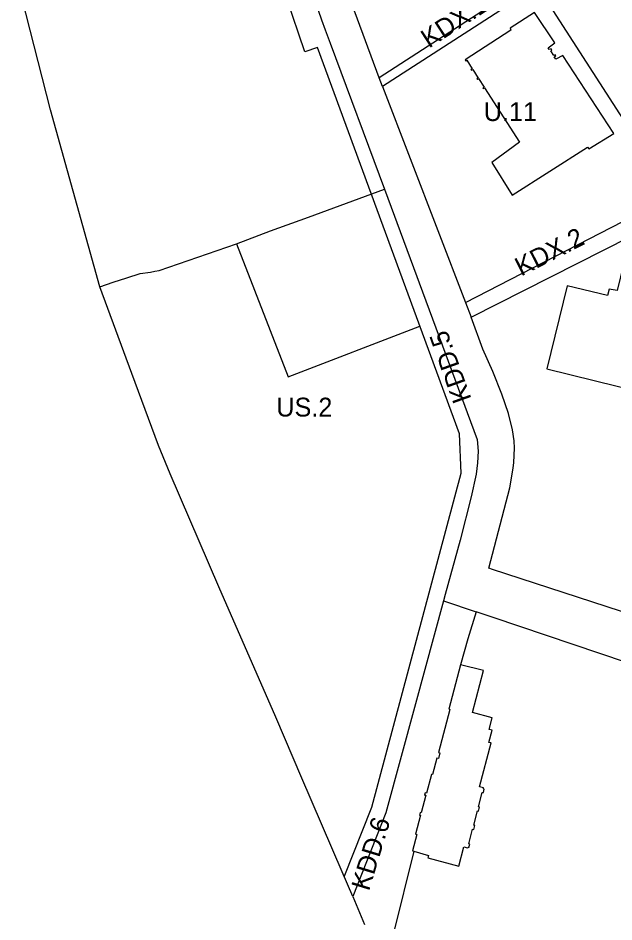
# Model space of a CAD drawing. Extents: x 7424052 to 7425705, y 5546602 to 5547569.
# Drawn here: x 7424707.9 to 7424865.9, y 5546961.1 to 5547200.9 of the extents above; entities that cross this region are included whole.
import ezdxf

# ---------------------------------------------------------------- set-up
doc = ezdxf.new("R2010")
doc.units = 0
for name, color, linetype in [('linia regulacyjna wysokości zabudowy', 7, 'Continuous'), ('linie rozgraniczające', 7, 'Continuous'), ('nieprzekraczalne linie zabudowy', 7, 'Continuous'), ('obowiazujace linie zabudowy', 7, 'Continuous'), ('przeznaczenia terenów', 7, 'Continuous')]:
    doc.layers.add(name, color=color, linetype=linetype)

msp = doc.modelspace()

# ---------------------------------------------------------------- linework, layer by layer
at = {"layer": 'linia regulacyjna wysokości zabudowy'}
msp.add_lwpolyline([(7424765.86, 5547141.04), (7424779.53, 5547105.72), (7424814.48, 5547119.2)], dxfattribs=at)
at = {"layer": 'linie rozgraniczające'}
for p, q in [((7424716.56, 5547176.59), (7424707.94, 5547210.43)), ((7424844.22, 5547211.34), (7424803.72, 5547185.05)), ((7424869.3, 5547172.76), (7424848.08, 5547205.67)), ((7424803.72, 5547185.05), (7424796.45, 5547204.69)), ((7424787.48, 5547203.06), (7424788.42, 5547200.44)), ((7424835.69, 5547202.88), (7424804.56, 5547182.77)), ((7424788.42, 5547200.44), (7424789.37, 5547197.83)), ((7424789.37, 5547197.83), (7424790.69, 5547194.3)), ((7424790.69, 5547194.3), (7424805.06, 5547155.51)), ((7424804.56, 5547182.77), (7424803.72, 5547185.05)), ((7424804.56, 5547182.77), (7424826.56, 5547125.51)), ((7424729.61, 5547129.62), (7424716.56, 5547176.59)), ((7424784.9, 5547148.15), (7424805.06, 5547155.51)), ((7424805.06, 5547155.51), (7424829.65, 5547089.09)), ((7424774.88, 5547144.49), (7424784.9, 5547148.15)), ((7424826.56, 5547125.51), (7424868.31, 5547146.93)), ((7424765.86, 5547141.04), (7424774.88, 5547144.49)), ((7424755.58, 5547137.48), (7424765.86, 5547141.04)), ((7424828.05, 5547121.6), (7424870.34, 5547142.98)), ((7424745.31, 5547133.93), (7424755.58, 5547137.48)), ((7424740.29, 5547133.16), (7424743.02, 5547133.57)), ((7424743.02, 5547133.57), (7424744.16, 5547133.75)), ((7424744.16, 5547133.75), (7424745.31, 5547133.93)), ((7424733.18, 5547130.88), (7424736.73, 5547132.02)), ((7424736.73, 5547132.02), (7424740.29, 5547133.16)), ((7424729.61, 5547129.62), (7424733.18, 5547130.88)), ((7424738.08, 5547106.67), (7424729.61, 5547129.62)), ((7424826.56, 5547125.51), (7424828.05, 5547121.6)), ((7424831.19, 5547113.14), (7424828.05, 5547121.6)), ((7424833.8, 5547107.14), (7424831.19, 5547113.14)), ((7424745.14, 5547087.58), (7424738.08, 5547106.67)), ((7424836.19, 5547101.2), (7424833.8, 5547107.14)), ((7424837.96, 5547096.03), (7424836.19, 5547101.2)), ((7424839.02, 5547091.68), (7424837.96, 5547096.03)), ((7424839.44, 5547088.76), (7424839.02, 5547091.68)), ((7424829.65, 5547089.09), (7424829.94, 5547086.06)), ((7424839.52, 5547086.84), (7424839.44, 5547088.76)), ((7424748.22, 5547080), (7424745.14, 5547087.58)), ((7424829.94, 5547086.06), (7424829.74, 5547082.92)), ((7424839.38, 5547083), (7424839.52, 5547086.84)), ((7424829.74, 5547082.92), (7424829.42, 5547079.97)), ((7424838.36, 5547076.31), (7424839.22, 5547081.54)), ((7424839.22, 5547081.54), (7424839.38, 5547083)), ((7424761.2, 5547050.01), (7424748.22, 5547080)), ((7424829.42, 5547079.97), (7424828.11, 5547073.91)), ((7424832.76, 5547054.97), (7424838.36, 5547076.31)), ((7424828.11, 5547073.91), (7424825.16, 5547062.46)), ((7424825.16, 5547062.46), (7424821.22, 5547047.97)), ((7424833.77, 5547054.64), (7424832.76, 5547054.97)), ((7424878.62, 5547040.03), (7424833.77, 5547054.64)), ((7424776.25, 5547015.45), (7424761.2, 5547050.01)), ((7424821.22, 5547047.97), (7424820.77, 5547046.36)), ((7424820.77, 5547046.36), (7424813.3, 5547018.98)), ((7424820.77, 5547046.36), (7424829.38, 5547043.45)), ((7424813.3, 5547018.98), (7424805.43, 5546990.04)), ((7424805.43, 5546990.04), (7424800.33, 5546977.11)), ((7424800.33, 5546977.11), (7424796.68, 5546967.84)), ((7424796.68, 5546967.84), (7424799.75, 5546960.49))]:
    msp.add_line(p, q, dxfattribs=at)
for points in [[(7424869.23, 5547029.94), (7424833.88, 5547041.92), (7424829.38, 5547043.45), (7424827.17, 5547036.2), (7424825.27, 5547029.34), (7424822.13, 5547017.6), (7424822.38, 5547017.53), (7424819.4, 5547006.12), (7424819.76, 5547005.98), (7424819.38, 5547004.52), (7424818.99, 5547004.59), (7424817.83, 5547000.21), (7424817.53, 5547000.29), (7424816.19, 5546995.34), (7424815.91, 5546995.41), (7424815.74, 5546994.8), (7424816.03, 5546994.73), (7424814.79, 5546990.06), (7424814.51, 5546990.13), (7424814.35, 5546989.5), (7424814.63, 5546989.43), (7424813.32, 5546984.42), (7424813.67, 5546984.35), (7424812.49, 5546980.02), (7424812.89, 5546979.91), (7424807.51, 5546958.13)], [(7424783.14, 5546999.26), (7424776.25, 5547015.45)], [(7424796.68, 5546967.84), (7424793.85, 5546974.41), (7424783.14, 5546999.26)]]:
    msp.add_lwpolyline(points, dxfattribs=at)
at = {"layer": 'nieprzekraczalne linie zabudowy'}
for p, q in [((7424783.94, 5547191.96), (7424774.34, 5547220.72)), ((7424787.32, 5547193.13), (7424783.94, 5547191.96)), ((7424824.94, 5547090.66), (7424787.32, 5547193.13)), ((7424831.6, 5547182.45), (7424840.87, 5547168)), ((7424825.38, 5547080.23), (7424824.94, 5547090.66)), ((7424801.73, 5546991.55), (7424825.38, 5547080.23)), ((7424794.43, 5546973.06), (7424801.73, 5546991.55))]:
    msp.add_line(p, q, dxfattribs=at)
at = {"layer": 'obowiazujace linie zabudowy'}
for points in [[(7424840.87, 5547168), (7424833.52, 5547162.6), (7424838.95, 5547153.99), (7424858.93, 5547166.73), (7424859.28, 5547166.22), (7424865.92, 5547170.35), (7424852.38, 5547191.04), (7424850.51, 5547190.02), (7424850.11, 5547190.64), (7424850.48, 5547190.91), (7424850.31, 5547191.19), (7424850.03, 5547191.04), (7424849.21, 5547192.28), (7424849.44, 5547192.47), (7424849.26, 5547192.74), (7424848.79, 5547192.63), (7424848.5, 5547193.08), (7424850.22, 5547194.37), (7424844.87, 5547202.45), (7424838.45, 5547198.28), (7424838.61, 5547197.75), (7424826.47, 5547189.84), (7424826.62, 5547189.47), (7424826.92, 5547189.75), (7424828.38, 5547187.47), (7424828.02, 5547187.31), (7424828.16, 5547187.1), (7424828.5, 5547187.32), (7424829.94, 5547185.04), (7424829.58, 5547184.89), (7424829.72, 5547184.68), (7424830.06, 5547184.88), (7424831.5, 5547182.61), (7424831.15, 5547182.46), (7424831.29, 5547182.25), (7424831.6, 5547182.45)], [(7424887.39, 5547134.46), (7424869.33, 5547139.19), (7424866.8, 5547128.69), (7424864.65, 5547129.03), (7424864.24, 5547127.34), (7424853.51, 5547129.93), (7424848.1, 5547107.91), (7424891.9, 5547097.08), (7424892.02, 5547097.52), (7424892.6, 5547100.01), (7424895.88, 5547099.43), (7424895.17, 5547096.76), (7424898.36, 5547095.95), (7424897.45, 5547092.28), (7424893.47, 5547076.73), (7424897.15, 5547075.81), (7424903.99, 5547074.05), (7424907.97, 5547089.61), (7424911.02, 5547088.78), (7424910.64, 5547087.2), (7424933.17, 5547081.48), (7424937.27, 5547097.62)], [(7424822.38, 5547017.53), (7424819.4, 5547006.12), (7424819.76, 5547005.98), (7424819.38, 5547004.52), (7424818.99, 5547004.59), (7424817.83, 5547000.21), (7424817.53, 5547000.29), (7424816.19, 5546995.34), (7424815.91, 5546995.41), (7424815.74, 5546994.8), (7424816.03, 5546994.73), (7424814.79, 5546990.06), (7424814.51, 5546990.13), (7424814.35, 5546989.5), (7424814.63, 5546989.43), (7424813.32, 5546984.42), (7424813.67, 5546984.35), (7424812.49, 5546980.02), (7424812.89, 5546979.91), (7424816.75, 5546978.79), (7424816.6, 5546978.13), (7424824.76, 5546975.89), (7424826.14, 5546981.02), (7424827.11, 5546980.76), (7424827.18, 5546980.97), (7424827.47, 5546980.89), (7424827.71, 5546981.8), (7424827.43, 5546981.89), (7424828.45, 5546985.75), (7424828.74, 5546985.69), (7424829.03, 5546986.75), (7424828.75, 5546986.84), (7424829.73, 5546990.59), (7424830.02, 5546990.53), (7424830.31, 5546991.59), (7424830.03, 5546991.67), (7424830.99, 5546995.47), (7424831.17, 5546995.5), (7424831.33, 5546995.47), (7424831.56, 5546996.39), (7424831.31, 5546996.46), (7424831.34, 5546996.67), (7424830.26, 5546996.95), (7424833.41, 5547008.63), (7424832.8, 5547008.78), (7424833.6, 5547011.97), (7424832.82, 5547012.18), (7424833.63, 5547015.25), (7424828.41, 5547016.66), (7424831.38, 5547027.84), (7424825.27, 5547029.34), (7424822.13, 5547017.6), (7424822.38, 5547017.53)]]:
    msp.add_lwpolyline(points, dxfattribs=at)

# ---------------------------------------------------------------- texts
at = {"layer": 'przeznaczenia terenów'}
for s, rotation, p in [('KDX.1', 33, (7424816.87, 5547192.83)), ('KDX.2', 26.9973, (7424841.31, 5547132.34)), ('KDD.5', 109.6626, (7424828.2, 5547099.9)), ('KDD.6', 73.0986, (7424800.97, 5546969.13))]:
    msp.add_text(s, height=5, rotation=rotation, dxfattribs=at).set_placement(p)
for s, p in [('U.11', (7424831.41, 5547173.63)), ('US.2', (7424776.4, 5547095.22))]:
    msp.add_text(s, height=5, dxfattribs=at).set_placement(p)

doc.saveas('drawing.dxf')
